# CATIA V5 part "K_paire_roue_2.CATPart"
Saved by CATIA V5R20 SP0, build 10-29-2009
Part number: paire_roue_2
Publications: "Corps principal", "Plan.2"
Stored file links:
  G:\Khaled_CFAO_2011\ST2M\ST2M_GR2\echouteau\Khaled\CAD_ThinkMotion\K_paire_roue_2.CATPart
  F:\2A\Proj Think Motion\trainv3\Version3\sql_general.CATProduct
  G:\Khaled_CFAO_2011\ST2M\ST2M_GR2\echouteau\Khaled\CAD_ThinkMotion\K_paire_roue_1.CATPart
  G:\Khaled_CFAO_2011\ST2M\ST2M_GR2\echouteau\Khaled\CAD_ThinkMotion\K_bogie_beam.CATPart

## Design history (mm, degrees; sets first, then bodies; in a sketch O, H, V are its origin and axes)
Set1
  Plane1: linked copy from another document
  Point1: linked copy from another document
Body1 (main body)
  Plane2: type OffsetPt, RefPlane Plane1, RefPoint Point1
  Line1: type Normal, RefPoint Point1, RefSkin Plane2, Start -150, End 150
  Plane3: type OffsetPt, RefPlane Plane2, RefPoint vertex of Line1
  Plane4: type OffsetPt, RefPlane Plane2, RefPoint vertex of Line1
  Line2: type Normal, RefPoint vertex of Line1, RefSkin Plane4, Start 0, End 100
